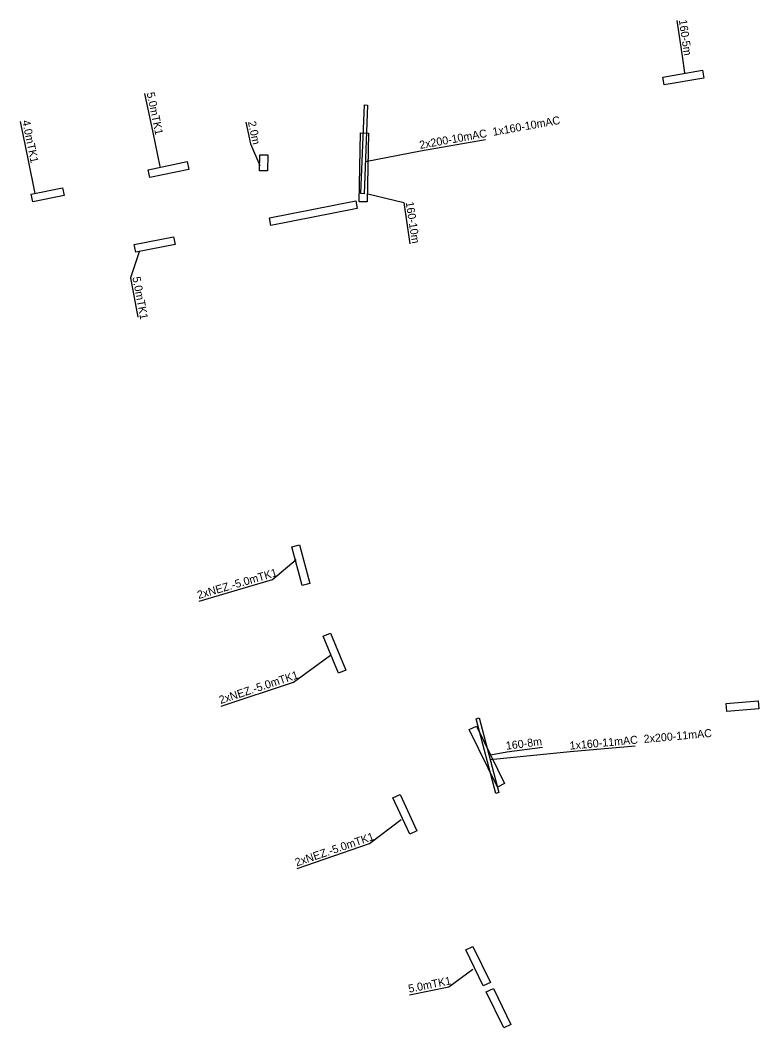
# Model space of a CAD drawing. Extents: x -732155 to -731960, y -1048709 to -1047981.
# Drawn here: x -732095.7 to -732003.5, y -1048497.7 to -1048371.8 of the extents above; entities that cross this region are included whole.
import ezdxf

# ---------------------------------------------------------------- set-up
doc = ezdxf.new("R2010")
doc.units = 0
doc.layers.add('Chránička', color=7, linetype='Continuous')
doc.layers.add('ST_CHRANICKA_POPIS', color=7, linetype='Continuous')

msp = doc.modelspace()

# ---------------------------------------------------------------- linework, layer by layer
at = {"layer": 'Chránička'}
for points in [[(-732015.264, -1048379.914), (-732015.434, -1048378.928), (-732010.507, -1048378.079), (-732010.337, -1048379.065), (-732015.264, -1048379.914)], [(-732052.717, -1048382.41), (-732052.317, -1048382.426), (-732052.76, -1048393.498), (-732053.159, -1048393.482), (-732052.717, -1048382.41)], [(-732053.198, -1048385.907), (-732052.199, -1048385.927), (-732052.372, -1048394.525), (-732053.371, -1048394.502), (-732053.198, -1048385.907)], [(-732065.803, -1048388.642), (-732064.803, -1048388.654), (-732064.828, -1048390.654), (-732065.828, -1048390.642), (-732065.803, -1048388.642)], [(-732079.541, -1048391.488), (-732079.745, -1048390.51), (-732074.851, -1048389.486), (-732074.647, -1048390.464), (-732079.541, -1048391.488)], [(-732094.148, -1048394.523), (-732094.348, -1048393.543), (-732090.429, -1048392.744), (-732090.229, -1048393.724), (-732094.148, -1048394.523)], [(-732064.406, -1048397.488), (-732064.6, -1048396.506), (-732053.815, -1048394.379), (-732053.621, -1048395.361), (-732064.406, -1048397.488)], [(-732081.272, -1048400.814), (-732081.466, -1048399.832), (-732076.56, -1048398.865), (-732076.366, -1048399.847), (-732081.272, -1048400.814)], [(-732059.54, -1048442.206), (-732060.506, -1048442.462), (-732061.783, -1048437.628), (-732060.817, -1048437.372), (-732059.54, -1048442.206)], [(-732055.047, -1048453.009), (-732055.971, -1048453.393), (-732057.889, -1048448.776), (-732056.965, -1048448.392), (-732055.047, -1048453.009)], [(-732003.532, -1048456.868), (-732003.452, -1048457.864), (-732007.439, -1048458.18), (-732007.519, -1048457.184), (-732003.532, -1048456.868)], [(-732036.301, -1048468.41), (-732038.781, -1048459.093), (-732038.395, -1048458.99), (-732035.915, -1048468.307), (-732036.301, -1048468.41)], [(-732039.618, -1048460.434), (-732038.72, -1048459.996), (-732035.216, -1048467.188), (-732036.114, -1048467.626), (-732039.618, -1048460.434)], [(-732046.162, -1048473.087), (-732047.07, -1048473.507), (-732049.169, -1048468.969), (-732048.261, -1048468.549), (-732046.162, -1048473.087)], [(-732036.972, -1048492.021), (-732037.87, -1048492.459), (-732040.062, -1048487.965), (-732039.164, -1048487.527), (-732036.972, -1048492.021)], [(-732037.505, -1048493.208), (-732036.607, -1048492.77), (-732034.416, -1048497.265), (-732035.314, -1048497.703), (-732037.505, -1048493.208)]]:
    msp.add_lwpolyline(points, close=True, dxfattribs=at)
at = {"layer": 'ST_CHRANICKA_POPIS'}
for points in [[(-732013.693, -1048371.845), (-732013.042, -1048376.328), (-732012.731, -1048378.394)], [(-732080.176, -1048380.966), (-732079.148, -1048385.869), (-732078.294, -1048390.106)], [(-732095.727, -1048384.461), (-732094.716, -1048389.367), (-732093.902, -1048393.488)], [(-732067.527, -1048384.58), (-732066.959, -1048387.265), (-732065.786, -1048389.993)], [(-732052.588, -1048389.459), (-732045.722, -1048388.158), (-732037.615, -1048386.706)], [(-732052.287, -1048393.497), (-732047.816, -1048394.592), (-732047.032, -1048399.749)], [(-732080.863, -1048400.757), (-732081.952, -1048403.995), (-732081.027, -1048408.918)], [(-732073.373, -1048444.38), (-732064.218, -1048441.708), (-732061.231, -1048439.177)], [(-732070.617, -1048457.497), (-732061.562, -1048454.504), (-732056.942, -1048451.143)], [(-732037.03, -1048464.175), (-732027.021, -1048463.201), (-732018.91, -1048462.468)], [(-732036.977, -1048463.597), (-732034.953, -1048463.217), (-732030.462, -1048462.633)], [(-732061.111, -1048477.787), (-732052.09, -1048474.692), (-732048.124, -1048471.665)], [(-732047.087, -1048493.57), (-732042.176, -1048492.581), (-732039.186, -1048490.366)]]:
    msp.add_lwpolyline(points, dxfattribs=at)

# ---------------------------------------------------------------- texts
for s, rotation, p in [('160-5m', 278.25454, (-732013.445, -1048371.809)), ('5.0mTK1', 281.84818, (-732079.932, -1048380.915)), ('2x200-10mAC  1x160-10mAC', 10.15438, (-732045.766, -1048387.912)), ('4.0mTK1', 281.64546, (-732095.482, -1048384.411)), ('2.0m', 281.94086, (-732067.282, -1048384.528)), ('160-10m', 278.6436, (-732047.569, -1048394.554)), ('5.0mTK1', 280.64231, (-732081.706, -1048403.949)), ('2xNEZ.-5.0mTK1', 16.26728, (-732073.443, -1048444.14)), ('2xNEZ.-5.0mTK1', 18.29353, (-732070.695, -1048457.26)), ('1x160-11mAC  2x200-11mAC', 5.16043, (-732027.044, -1048462.952)), ('160-8m', 7.40704, (-732034.985, -1048462.969)), ('2xNEZ.-5.0mTK1', 18.93733, (-732061.192, -1048477.551)), ('5.0mTK1', 11.38508, (-732047.136, -1048493.325))]:
    msp.add_text(s, height=1, rotation=rotation, dxfattribs=at).set_placement(p)

doc.saveas('drawing.dxf')
